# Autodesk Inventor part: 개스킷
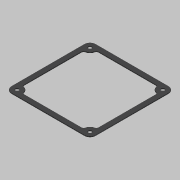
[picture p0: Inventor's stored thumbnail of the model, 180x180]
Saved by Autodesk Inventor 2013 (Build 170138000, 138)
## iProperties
Created: 2019-04
Part Number: 개스킷
Material: 고무
Document SubType Name: Modeling
Designer: mduedu
Density: 1 g/cm^3
Author: mduedu
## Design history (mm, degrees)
sketch "스케치1"
  geometry: L1 (52.5, 52.5)-(-52.5, 52.5); L2 (-52.5, 52.5)-(-52.5, -52.5); L3 (-52.5, -52.5)-(52.5, -52.5); L4 (52.5, -52.5)-(52.5, 52.5); L5 (52.5, 52.5)-(-52.5, -52.5); L6 (-52.5, 52.5)-(52.5, -52.5); 1 further point
  constraints: 12 end point, 2 midpoint, 2 parallel, 1 horizontal, 1 perpendicular
  dimensions: "d0" = 105 distance of L3.end L2.end; "d1" = 105 distance of L2.end L1.end
extrude "돌출1" new body sketch "스케치1" distance "d2" = 1; taper "d3" = 0 deg
sketch "스케치2"
  geometry: L1 (-52.5, -52.5)-(52.5, -52.5) reference; L2 (52.5, -52.5)-(52.5, 52.5) reference; L3 (52.5, 52.5)-(-52.5, 52.5) reference; L4 (-52.5, 52.5)-(-52.5, -52.5) reference; L5 (-46.5, 46.5)-(46.5, 46.5); L6 (46.5, 46.5)-(46.5, -46.5); L7 (46.5, -46.5)-(-46.5, -46.5); L8 (-46.5, -46.5)-(-46.5, 46.5); 1 further point
  constraints: 8 end point, 3 other
  dimensions: "d4" = 6 distance between parallel lines of L5 L3
extrude "돌출2" cut sketch "스케치2" stored distance "d5" = 1; taper "d6" = 0 deg
fillet "모깎기1" dims "d7" = 7
sketch "스케치3"
  geometry: A1 r 7 centre (-45.5, 45.5) between (-45.5, 52.5) and (-52.5, 45.5) reference; A2 r 7 centre (-45.5, -45.5) between (-52.5, -45.5) and (-45.5, -52.5) reference; A3 r 7 centre (45.5, -45.5) between (45.5, -52.5) and (52.5, -45.5) reference; A4 r 7 centre (45.5, 45.5) between (52.5, 45.5) and (45.5, 52.5) reference; 5 further points
  constraints: 4 coincident, 4 vertical alignment, 8 other
extrude "돌출3" join sketch "스케치3" stored distance "d8" = 1; taper "d9" = 0 deg
fillet "모깎기2" dims "d10" = 3
sketch "스케치4"
  geometry: A1 r 7 centre (-45.5, 45.5) between (-45.5, 52.5) and (-52.5, 45.5) reference; A2 r 7 centre (45.5, 45.5) between (52.5, 45.5) and (45.5, 52.5) reference; A3 r 7 centre (45.5, -45.5) between (45.5, -52.5) and (52.5, -45.5) reference; A4 r 7 centre (-45.5, -45.5) between (-52.5, -45.5) and (-45.5, -52.5) reference; 5 further points
  constraints: 4 coincident
hole "구멍1" sketch "스케치4" at (-45.5, 45.5), (45.5, 45.5), (45.5, -45.5), (-45.5, -45.5) diameter "d11" = 4.5; stored, may be unused: countersink angle "d15" = 90 deg, drill point angle "d17" = 118 deg; dims "d12" = 6, "d13" = 4, "d14" = 2, "d16" = 8
node "솔리드1"
node "투영된 루프1"
